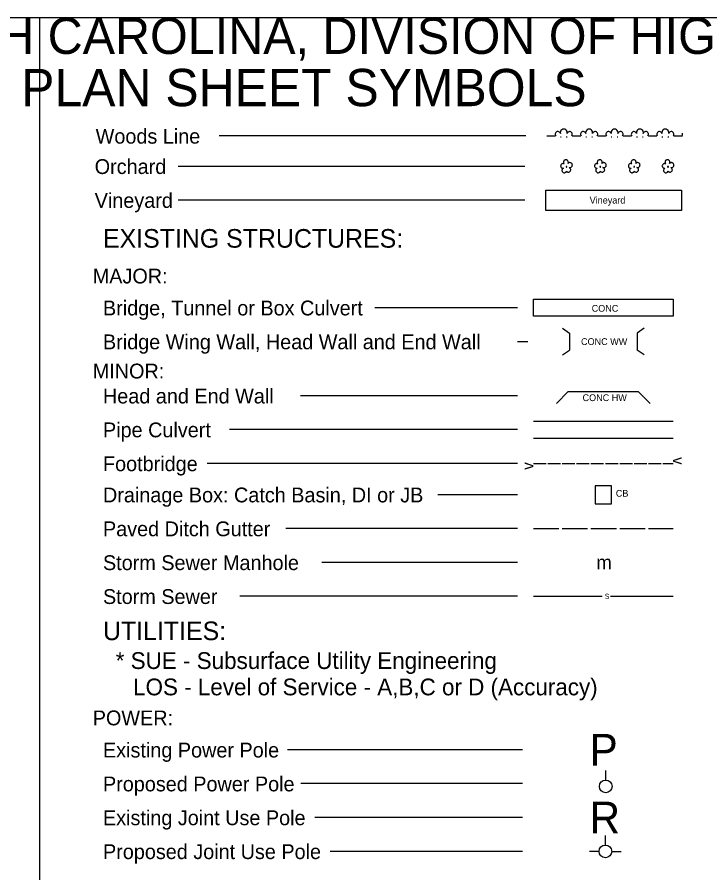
# Model space of a CAD drawing. Extents: x 2025847 to 2026166, y 840763 to 840870.
# Drawn here: x 2025913.87 to 2025948.28, y 840805.81 to 840848.31 of the extents above; entities that cross this region are included whole.
import ezdxf

# ---------------------------------------------------------------- set-up
doc = ezdxf.new("R2010")
doc.units = 0
for name, color, linetype in [('Sheet_Plan_CELL', 7, 'Continuous'), ('Sheet_Symbology_CELL', 7, 'Continuous'), ('z - Construction', 7, 'Continuous')]:
    doc.layers.add(name, color=color, linetype=linetype)

msp = doc.modelspace()

# ---------------------------------------------------------------- linework, layer by layer
at = {"layer": 'Sheet_Plan_CELL'}
msp.add_line((2025982.682, 840848.272), (2025847.265, 840848.272), dxfattribs=at)
at = {"layer": 'Sheet_Symbology_CELL'}
for p, q in [((2025939.138, 840842.402), (2025923.91, 840842.402)), ((2025940.18, 840842.402), (2025940.601, 840842.402)), ((2025940.849, 840842.36), (2025940.891, 840842.36)), ((2025941.143, 840842.36), (2025941.185, 840842.36)), ((2025941.441, 840842.402), (2025941.862, 840842.402)), ((2025942.11, 840842.36), (2025942.152, 840842.36)), ((2025942.404, 840842.36), (2025942.446, 840842.36)), ((2025942.703, 840842.402), (2025943.123, 840842.402)), ((2025943.371, 840842.36), (2025943.413, 840842.36)), ((2025943.665, 840842.36), (2025943.707, 840842.36)), ((2025943.964, 840842.402), (2025944.384, 840842.402)), ((2025944.632, 840842.36), (2025944.674, 840842.36)), ((2025944.927, 840842.36), (2025944.969, 840842.36)), ((2025945.225, 840842.402), (2025945.645, 840842.402)), ((2025945.893, 840842.36), (2025945.935, 840842.36)), ((2025946.188, 840842.36), (2025946.23, 840842.36)), ((2025946.486, 840842.402), (2025946.907, 840842.402)), ((2025939.091, 840840.895), (2025921.86, 840840.895)), ((2025939.091, 840839.214), (2025921.86, 840839.214)), ((2025938.728, 840833.874), (2025931.63, 840833.874)), ((2025940.952, 840832.854), (2025941.297, 840832.613)), ((2025945.004, 840832.854), (2025944.66, 840832.613)), ((2025941.297, 840832.613), (2025941.297, 840831.772)), ((2025944.66, 840832.613), (2025944.66, 840831.772)), ((2025938.728, 840832.193), (2025939.231, 840832.193)), ((2025940.952, 840831.531), (2025941.297, 840831.772)), ((2025945.004, 840831.531), (2025944.66, 840831.772)), ((2025938.728, 840829.503), (2025927.941, 840829.503)), ((2025940.649, 840829.118), (2025941.244, 840829.713)), ((2025941.244, 840829.713), (2025944.712, 840829.713)), ((2025944.712, 840829.713), (2025945.307, 840829.118)), ((2025939.51, 840828.241), (2025946.446, 840828.241)), ((2025938.728, 840827.821), (2025924.419, 840827.821)), ((2025939.51, 840827.401), (2025946.446, 840827.401)), ((2025938.728, 840826.139), (2025923.302, 840826.139)), ((2025939.51, 840826.139), (2025940.141, 840826.139)), ((2025940.225, 840826.139), (2025940.855, 840826.139)), ((2025940.939, 840826.139), (2025941.57, 840826.139)), ((2025941.654, 840826.139), (2025942.285, 840826.139)), ((2025942.369, 840826.139), (2025942.999, 840826.139)), ((2025943.083, 840826.139), (2025943.714, 840826.139)), ((2025943.798, 840826.139), (2025944.429, 840826.139)), ((2025944.513, 840826.139), (2025945.143, 840826.139)), ((2025945.227, 840826.139), (2025945.858, 840826.139)), ((2025945.942, 840826.139), (2025946.446, 840826.139)), ((2025938.728, 840824.589), (2025934.76, 840824.589)), ((2025938.728, 840822.908), (2025927.213, 840822.908)), ((2025939.51, 840822.908), (2025940.771, 840822.908)), ((2025940.939, 840822.908), (2025942.2, 840822.908)), ((2025942.369, 840822.908), (2025943.63, 840822.908)), ((2025943.798, 840822.908), (2025945.059, 840822.908)), ((2025945.227, 840822.908), (2025946.446, 840822.908)), ((2025938.728, 840821.226), (2025929.002, 840821.226)), ((2025938.728, 840819.545), (2025924.922, 840819.545)), ((2025939.51, 840819.545), (2025942.917, 840819.545)), ((2025943.338, 840819.545), (2025946.446, 840819.545)), ((2025938.962, 840811.92), (2025927.301, 840811.92)), ((2025943.101, 840810.416), (2025943.101, 840810.889)), ((2025938.962, 840810.239), (2025927.955, 840810.239)), ((2025938.962, 840808.557), (2025928.662, 840808.557)), ((2025943.083, 840807.192), (2025943.083, 840807.665)), ((2025938.962, 840806.876), (2025929.418, 840806.876)), ((2025942.768, 840806.877), (2025942.295, 840806.877)), ((2025943.399, 840806.877), (2025943.871, 840806.877))]:
    msp.add_line(p, q, dxfattribs=at)
for points in [[(2025941.23, 840841.042), (2025941.243, 840841.067), (2025941.247, 840841.093), (2025941.243, 840841.118), (2025941.238, 840841.143), (2025941.226, 840841.164), (2025941.213, 840841.185), (2025941.192, 840841.202), (2025941.171, 840841.215), (2025941.142, 840841.223), (2025941.121, 840841.223), (2025941.095, 840841.219), (2025941.07, 840841.21), (2025941.049, 840841.198), (2025941.028, 840841.181), (2025941.016, 840841.156), (2025941.007, 840841.135), (2025941.003, 840841.11), (2025941.003, 840841.084), (2025941.007, 840841.059), (2025941.02, 840841.038), (2025941.037, 840841.013), (2025941.016, 840841.025), (2025940.99, 840841.03), (2025940.965, 840841.03), (2025940.944, 840841.021), (2025940.923, 840841.013), (2025940.902, 840840.996), (2025940.885, 840840.979), (2025940.873, 840840.958), (2025940.868, 840840.937), (2025940.864, 840840.908), (2025940.868, 840840.887), (2025940.877, 840840.866), (2025940.894, 840840.845), (2025940.906, 840840.828), (2025940.927, 840840.815), (2025940.953, 840840.803), (2025940.974, 840840.798), (2025940.999, 840840.798), (2025940.978, 840840.79), (2025940.957, 840840.773), (2025940.944, 840840.756), (2025940.936, 840840.731), (2025940.927, 840840.706), (2025940.927, 840840.685), (2025940.932, 840840.66), (2025940.944, 840840.639), (2025940.957, 840840.618), (2025940.974, 840840.601), (2025940.995, 840840.588), (2025941.016, 840840.58), (2025941.041, 840840.58), (2025941.066, 840840.58), (2025941.087, 840840.584), (2025941.108, 840840.601), (2025941.129, 840840.613), (2025941.15, 840840.651)], [(2025941.15, 840840.651), (2025941.201, 840840.622), (2025941.226, 840840.613), (2025941.251, 840840.609), (2025941.276, 840840.613), (2025941.297, 840840.622), (2025941.318, 840840.634), (2025941.339, 840840.651), (2025941.352, 840840.672), (2025941.36, 840840.693), (2025941.369, 840840.719), (2025941.365, 840840.744), (2025941.36, 840840.769), (2025941.344, 840840.794), (2025941.331, 840840.811), (2025941.31, 840840.824), (2025941.285, 840840.836), (2025941.31, 840840.832), (2025941.339, 840840.832), (2025941.36, 840840.84), (2025941.386, 840840.853), (2025941.407, 840840.866), (2025941.423, 840840.887), (2025941.436, 840840.912), (2025941.44, 840840.937), (2025941.444, 840840.962), (2025941.44, 840840.988), (2025941.432, 840841.013), (2025941.415, 840841.034), (2025941.394, 840841.055), (2025941.373, 840841.067), (2025941.348, 840841.076), (2025941.322, 840841.08), (2025941.297, 840841.08), (2025941.272, 840841.072), (2025941.251, 840841.059), (2025941.23, 840841.042)], [(2025942.912, 840841.042), (2025942.924, 840841.067), (2025942.928, 840841.093), (2025942.924, 840841.118), (2025942.92, 840841.143), (2025942.907, 840841.164), (2025942.895, 840841.185), (2025942.874, 840841.202), (2025942.853, 840841.215), (2025942.823, 840841.223), (2025942.802, 840841.223), (2025942.777, 840841.219), (2025942.752, 840841.21), (2025942.731, 840841.198), (2025942.71, 840841.181), (2025942.697, 840841.156), (2025942.689, 840841.135), (2025942.685, 840841.11), (2025942.685, 840841.084), (2025942.689, 840841.059), (2025942.701, 840841.038), (2025942.718, 840841.013), (2025942.697, 840841.025), (2025942.672, 840841.03), (2025942.647, 840841.03), (2025942.626, 840841.021), (2025942.605, 840841.013), (2025942.584, 840840.996), (2025942.567, 840840.979), (2025942.554, 840840.958), (2025942.55, 840840.937), (2025942.546, 840840.908), (2025942.55, 840840.887), (2025942.558, 840840.866), (2025942.575, 840840.845), (2025942.588, 840840.828), (2025942.609, 840840.815), (2025942.634, 840840.803), (2025942.655, 840840.798), (2025942.68, 840840.798), (2025942.659, 840840.79), (2025942.638, 840840.773), (2025942.626, 840840.756), (2025942.617, 840840.731), (2025942.609, 840840.706), (2025942.609, 840840.685), (2025942.613, 840840.66), (2025942.626, 840840.639), (2025942.638, 840840.618), (2025942.655, 840840.601), (2025942.676, 840840.588), (2025942.697, 840840.58), (2025942.722, 840840.58), (2025942.748, 840840.58), (2025942.769, 840840.584), (2025942.79, 840840.601), (2025942.811, 840840.613), (2025942.832, 840840.651)], [(2025942.832, 840840.651), (2025942.882, 840840.622), (2025942.907, 840840.613), (2025942.933, 840840.609), (2025942.958, 840840.613), (2025942.979, 840840.622), (2025943, 840840.634), (2025943.021, 840840.651), (2025943.033, 840840.672), (2025943.042, 840840.693), (2025943.05, 840840.719), (2025943.046, 840840.744), (2025943.042, 840840.769), (2025943.025, 840840.794), (2025943.012, 840840.811), (2025942.991, 840840.824), (2025942.966, 840840.836), (2025942.991, 840840.832), (2025943.021, 840840.832), (2025943.042, 840840.84), (2025943.067, 840840.853), (2025943.088, 840840.866), (2025943.105, 840840.887), (2025943.118, 840840.912), (2025943.122, 840840.937), (2025943.126, 840840.962), (2025943.122, 840840.988), (2025943.113, 840841.013), (2025943.097, 840841.034), (2025943.076, 840841.055), (2025943.055, 840841.067), (2025943.029, 840841.076), (2025943.004, 840841.08), (2025942.979, 840841.08), (2025942.954, 840841.072), (2025942.933, 840841.059), (2025942.912, 840841.042)], [(2025944.593, 840841.042), (2025944.606, 840841.067), (2025944.61, 840841.093), (2025944.606, 840841.118), (2025944.602, 840841.143), (2025944.589, 840841.164), (2025944.576, 840841.185), (2025944.555, 840841.202), (2025944.534, 840841.215), (2025944.505, 840841.223), (2025944.484, 840841.223), (2025944.459, 840841.219), (2025944.433, 840841.21), (2025944.412, 840841.198), (2025944.391, 840841.181), (2025944.379, 840841.156), (2025944.37, 840841.135), (2025944.366, 840841.11), (2025944.366, 840841.084), (2025944.37, 840841.059), (2025944.383, 840841.038), (2025944.4, 840841.013), (2025944.379, 840841.025), (2025944.354, 840841.03), (2025944.328, 840841.03), (2025944.307, 840841.021), (2025944.286, 840841.013), (2025944.265, 840840.996), (2025944.248, 840840.979), (2025944.236, 840840.958), (2025944.232, 840840.937), (2025944.227, 840840.908), (2025944.232, 840840.887), (2025944.24, 840840.866), (2025944.257, 840840.845), (2025944.269, 840840.828), (2025944.29, 840840.815), (2025944.316, 840840.803), (2025944.337, 840840.798), (2025944.362, 840840.798), (2025944.341, 840840.79), (2025944.32, 840840.773), (2025944.307, 840840.756), (2025944.299, 840840.731), (2025944.29, 840840.706), (2025944.29, 840840.685), (2025944.295, 840840.66), (2025944.307, 840840.639), (2025944.32, 840840.618), (2025944.337, 840840.601), (2025944.358, 840840.588), (2025944.379, 840840.58), (2025944.404, 840840.58), (2025944.429, 840840.58), (2025944.45, 840840.584), (2025944.471, 840840.601), (2025944.492, 840840.613), (2025944.513, 840840.651)], [(2025944.513, 840840.651), (2025944.564, 840840.622), (2025944.589, 840840.613), (2025944.614, 840840.609), (2025944.639, 840840.613), (2025944.66, 840840.622), (2025944.681, 840840.634), (2025944.702, 840840.651), (2025944.715, 840840.672), (2025944.723, 840840.693), (2025944.732, 840840.719), (2025944.728, 840840.744), (2025944.723, 840840.769), (2025944.707, 840840.794), (2025944.694, 840840.811), (2025944.673, 840840.824), (2025944.648, 840840.836), (2025944.673, 840840.832), (2025944.702, 840840.832), (2025944.723, 840840.84), (2025944.749, 840840.853), (2025944.77, 840840.866), (2025944.787, 840840.887), (2025944.799, 840840.912), (2025944.803, 840840.937), (2025944.808, 840840.962), (2025944.803, 840840.988), (2025944.795, 840841.013), (2025944.778, 840841.034), (2025944.757, 840841.055), (2025944.736, 840841.067), (2025944.711, 840841.076), (2025944.686, 840841.08), (2025944.66, 840841.08), (2025944.635, 840841.072), (2025944.614, 840841.059), (2025944.593, 840841.042)], [(2025946.275, 840841.042), (2025946.287, 840841.067), (2025946.292, 840841.093), (2025946.287, 840841.118), (2025946.283, 840841.143), (2025946.27, 840841.164), (2025946.258, 840841.185), (2025946.237, 840841.202), (2025946.216, 840841.215), (2025946.186, 840841.223), (2025946.165, 840841.223), (2025946.14, 840841.219), (2025946.115, 840841.21), (2025946.094, 840841.198), (2025946.073, 840841.181), (2025946.06, 840841.156), (2025946.052, 840841.135), (2025946.048, 840841.11), (2025946.048, 840841.084), (2025946.052, 840841.059), (2025946.064, 840841.038), (2025946.081, 840841.013), (2025946.06, 840841.025), (2025946.035, 840841.03), (2025946.01, 840841.03), (2025945.989, 840841.021), (2025945.968, 840841.013), (2025945.947, 840840.996), (2025945.93, 840840.979), (2025945.917, 840840.958), (2025945.913, 840840.937), (2025945.909, 840840.908), (2025945.913, 840840.887), (2025945.922, 840840.866), (2025945.938, 840840.845), (2025945.951, 840840.828), (2025945.972, 840840.815), (2025945.997, 840840.803), (2025946.018, 840840.798), (2025946.043, 840840.798), (2025946.022, 840840.79), (2025946.001, 840840.773), (2025945.989, 840840.756), (2025945.98, 840840.731), (2025945.972, 840840.706), (2025945.972, 840840.685), (2025945.976, 840840.66), (2025945.989, 840840.639), (2025946.001, 840840.618), (2025946.018, 840840.601), (2025946.039, 840840.588), (2025946.06, 840840.58), (2025946.086, 840840.58), (2025946.111, 840840.58), (2025946.132, 840840.584), (2025946.153, 840840.601), (2025946.174, 840840.613), (2025946.195, 840840.651)], [(2025946.195, 840840.651), (2025946.245, 840840.622), (2025946.27, 840840.613), (2025946.296, 840840.609), (2025946.321, 840840.613), (2025946.342, 840840.622), (2025946.363, 840840.634), (2025946.384, 840840.651), (2025946.397, 840840.672), (2025946.405, 840840.693), (2025946.413, 840840.719), (2025946.409, 840840.744), (2025946.405, 840840.769), (2025946.388, 840840.794), (2025946.376, 840840.811), (2025946.355, 840840.824), (2025946.329, 840840.836), (2025946.355, 840840.832), (2025946.384, 840840.832), (2025946.405, 840840.84), (2025946.43, 840840.853), (2025946.451, 840840.866), (2025946.468, 840840.887), (2025946.481, 840840.912), (2025946.485, 840840.937), (2025946.489, 840840.962), (2025946.485, 840840.988), (2025946.476, 840841.013), (2025946.46, 840841.034), (2025946.439, 840841.055), (2025946.418, 840841.067), (2025946.392, 840841.076), (2025946.367, 840841.08), (2025946.342, 840841.08), (2025946.317, 840841.072), (2025946.296, 840841.059), (2025946.275, 840841.042)], [(2025941.159, 840840.895), (2025941.146, 840840.895), (2025941.138, 840840.891), (2025941.129, 840840.887), (2025941.129, 840840.874), (2025941.129, 840840.866), (2025941.138, 840840.857), (2025941.15, 840840.857), (2025941.159, 840840.857), (2025941.167, 840840.866), (2025941.171, 840840.878), (2025941.167, 840840.887), (2025941.159, 840840.895)], [(2025942.84, 840840.895), (2025942.827, 840840.895), (2025942.819, 840840.891), (2025942.811, 840840.887), (2025942.811, 840840.874), (2025942.811, 840840.866), (2025942.819, 840840.857), (2025942.832, 840840.857), (2025942.84, 840840.857), (2025942.849, 840840.866), (2025942.853, 840840.878), (2025942.849, 840840.887), (2025942.84, 840840.895)], [(2025944.522, 840840.895), (2025944.509, 840840.895), (2025944.501, 840840.891), (2025944.492, 840840.887), (2025944.492, 840840.874), (2025944.492, 840840.866), (2025944.501, 840840.857), (2025944.513, 840840.857), (2025944.522, 840840.857), (2025944.53, 840840.866), (2025944.534, 840840.878), (2025944.53, 840840.887), (2025944.522, 840840.895)], [(2025946.203, 840840.895), (2025946.191, 840840.895), (2025946.182, 840840.891), (2025946.174, 840840.887), (2025946.174, 840840.874), (2025946.174, 840840.866), (2025946.182, 840840.857), (2025946.195, 840840.857), (2025946.203, 840840.857), (2025946.212, 840840.866), (2025946.216, 840840.878), (2025946.212, 840840.887), (2025946.203, 840840.895)], [(2025940.133, 840839.718), (2025946.859, 840839.718), (2025946.859, 840838.709), (2025940.133, 840838.709), (2025940.133, 840839.718)], [(2025939.51, 840834.294), (2025946.446, 840834.294), (2025946.446, 840833.454), (2025939.51, 840833.454), (2025939.51, 840834.294)]]:
    msp.add_lwpolyline(points, dxfattribs=at)
msp.add_lwpolyline([(2025942.574, 840824.143), (2025943.382, 840824.143), (2025943.382, 840825.037), (2025942.574, 840825.037)], close=True, dxfattribs=at)
for centre in [(2025943.101, 840810.101), (2025943.083, 840806.876)]:
    msp.add_circle(centre, 0.315, dxfattribs=at)
for centre, radius, start, end in [((2025941.017, 840842.572), 0.173, 345.9638, 194.0362), ((2025942.278, 840842.572), 0.173, 345.9638, 194.0362), ((2025943.539, 840842.572), 0.173, 345.9638, 194.0362), ((2025944.8, 840842.572), 0.173, 345.9638, 194.0362), ((2025946.061, 840842.572), 0.173, 345.9638, 194.0362), ((2025940.723, 840842.488), 0.133, 18.435, 219.2315), ((2025941.311, 840842.488), 0.133, 320.7685, 161.5651), ((2025941.984, 840842.488), 0.133, 18.435, 219.2315), ((2025942.572, 840842.488), 0.133, 320.7685, 161.5651), ((2025943.245, 840842.488), 0.133, 18.435, 219.2315), ((2025943.833, 840842.488), 0.133, 320.7685, 161.5651), ((2025944.506, 840842.488), 0.133, 18.435, 219.2315), ((2025945.094, 840842.488), 0.133, 320.7685, 161.5651), ((2025945.767, 840842.488), 0.133, 18.435, 219.2315), ((2025946.356, 840842.488), 0.133, 320.7685, 161.5651), ((2025947.028, 840842.488), 0.133, 156.251, 203.749)]:
    msp.add_arc(centre, radius, start, end, dxfattribs=at)
at = {"layer": 'z - Construction'}
msp.add_line((2025914.974, 840848.272), (2025914.972, 840762.856), dxfattribs=at)

# ---------------------------------------------------------------- texts
at = {"layer": 'Sheet_Symbology_CELL'}
for s, height, p in [('STATE OF NORTH CAROLINA, DIVISION OF HIGHWAYS', 1.80087, (2025893.712, 840846.478)), ('CONVENTIONAL  PLAN SHEET SYMBOLS', 1.85243, (2025893.148, 840843.882)), ('Woods Line', 0.7357, (2025917.769, 840842.022)), ('Orchard', 0.7357, (2025917.721, 840840.515)), ('Vineyard', 0.7357, (2025917.721, 840838.833)), ('EXISTING STRUCTURES:', 0.92486, (2025918.132, 840836.855)), ('MAJOR:', 0.7357, (2025917.625, 840835.079)), ('Bridge, Tunnel or Box Culvert', 0.73569, (2025918.132, 840833.492)), ('CONC', 0.3363, (2025942.405, 840833.675)), ('Bridge Wing Wall, Head Wall and End Wall', 0.73569, (2025918.132, 840831.81)), ('MINOR:', 0.7357, (2025917.625, 840830.361)), ('Head and End Wall', 0.73569, (2025918.132, 840829.12)), ('CONC HW', 0.3363, (2025941.952, 840829.237)), ('Pipe Culvert', 0.73569, (2025918.132, 840827.439)), ('Footbridge', 0.7357, (2025918.133, 840825.758)), ('Drainage Box: Catch Basin, DI or JB', 0.73569, (2025918.133, 840824.208)), ('CB', 0.3363, (2025943.603, 840824.49)), ('Paved Ditch Gutter', 0.73569, (2025918.133, 840822.525)), ('Storm Sewer Manhole', 0.73569, (2025918.133, 840820.844)), ('m', 0.694, (2025942.631, 840820.879)), ('Storm Sewer', 0.73569, (2025918.133, 840819.162)), ('S', 0.252, (2025943.052, 840819.418)), ('UTILITIES:', 0.9249, (2025918.132, 840817.366)), ('* SUE - Subsurface Utility Engineering', 0.83238, (2025918.766, 840815.934)), ('LOS - Level of Service - A,B,C or D (Accuracy) ', 0.83238, (2025919.629, 840814.626)), ('POWER:', 0.7357, (2025917.625, 840813.136)), ('P', 1.576, (2025942.295, 840811.132)), ('Existing Power Pole', 0.73569, (2025918.133, 840811.539)), ('Proposed Power Pole', 0.73569, (2025918.133, 840809.857)), ('R', 1.576, (2025942.295, 840807.769)), ('Existing Joint Use Pole', 0.73569, (2025918.133, 840808.177)), ('Proposed Joint Use Pole', 0.73569, (2025918.134, 840806.494))]:
    msp.add_text(s, height=height, dxfattribs=at).set_placement(p)
for s, height, rotation, p in [('Vineyard', 0.3363, 0, (2025942.304, 840839.045)), ('CONC WW', 0.3363, 0, (2025941.875, 840832.024)), ('v', 0.555, 89.7591, (2025939.509, 840825.825)), ('v', 0.555, 270.2409, (2025946.445, 840826.454))]:
    msp.add_text(s, height=height, rotation=rotation, dxfattribs=at).set_placement(p)

doc.saveas('drawing.dxf')
